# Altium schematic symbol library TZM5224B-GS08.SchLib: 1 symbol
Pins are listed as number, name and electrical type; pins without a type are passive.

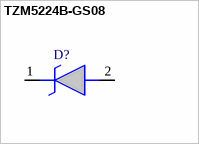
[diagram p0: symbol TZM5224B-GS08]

## TZM5224B-GS08
designator D?
Vishay TZM5224B-GS08 Zener Diode, 2.8V 5% 500 mW SMT 2-Pin SOD-80; Geometry.Height: 1.6mm
footprint BAQ33GS08
pins: 1 K, 2 A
